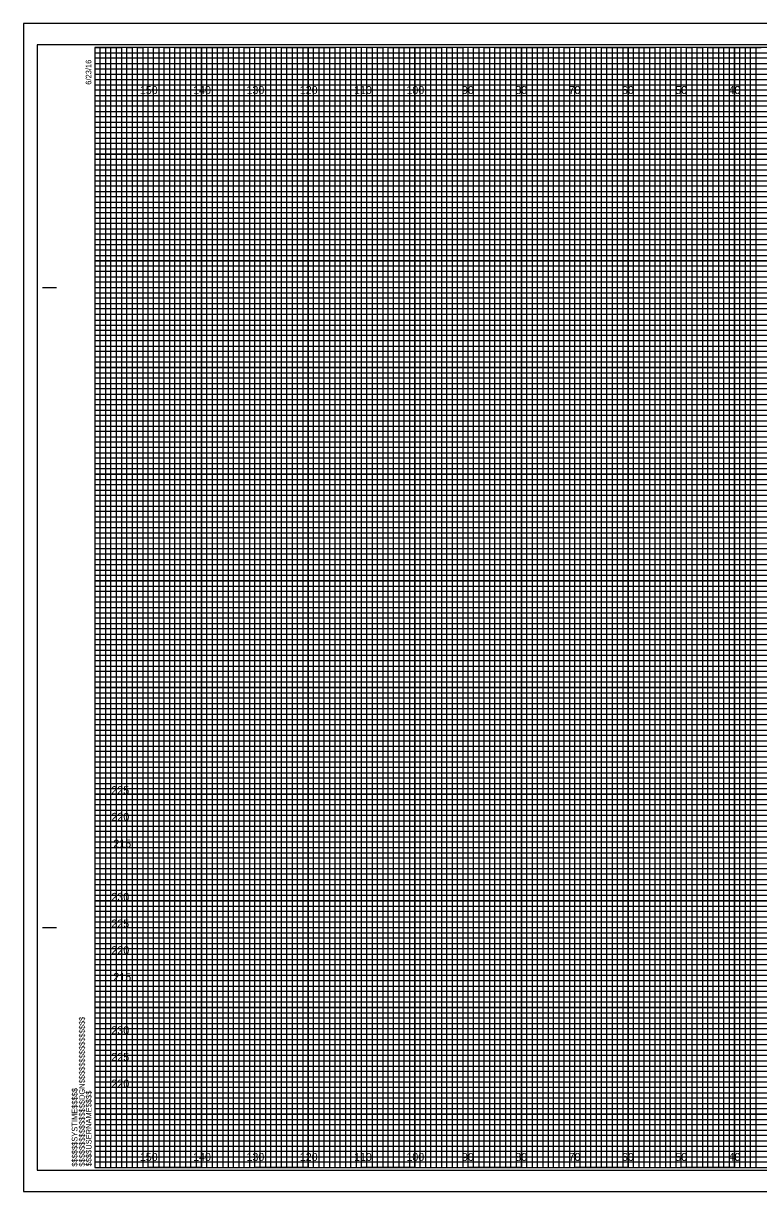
# Model space of a CAD drawing. Extents: x -13 to 323, y -5 to 434.
# Drawn here: x -13.4 to 124.5, y 215.5 to 434.5 of the extents above; entities that cross this region are included whole.
import ezdxf

# ---------------------------------------------------------------- set-up
doc = ezdxf.new("R2010")
doc.units = 0
for name, color, linetype in [('Prop XS Elevation Labels', 7, 'Continuous'), ('Prop XS Offset Labels', 7, 'Continuous'), ('Sheet Cross Section CELL', 7, 'Continuous'), ('Sheet Cross Section Grid Major CELL', 7, 'Continuous'), ('Sheet Cross Section Grid Middle CELL', 7, 'Continuous'), ('Sheet Cross Section Grid Minor 1 CELL', 7, 'Continuous'), ('Sheet Cross Section Grid Minor 2 CELL', 7, 'Continuous'), ('Sheet Cutting Line CELL', 7, 'Continuous'), ('Sheet DOT Grid CELL', 7, 'Continuous'), ('Sheet Plot Border Inside CELL', 7, 'Continuous'), ('Sheet Plot Border Outside CELL', 7, 'Continuous')]:
    doc.layers.add(name, color=color, linetype=linetype)

msp = doc.modelspace()

# ---------------------------------------------------------------- linework, layer by layer
at = {"layer": 'Sheet Cross Section CELL'}
for p, q in [((-9.8, 385), (-7.3, 385)), ((-9.7, 385), (-7.2, 385)), ((-9.8, 265), (-7.3, 265)), ((-9.7, 265), (-7.2, 265)), ((0, 220), (0, 220)), ((0, 220), (0, 220)), ((0, 220), (0, 220)), ((0, 220), (0, 220)), ((0, 220), (0, 220)), ((0, 220), (0, 220)), ((0, 220), (0, 220))]:
    msp.add_line(p, q, dxfattribs=at)
msp.add_lwpolyline([(320, 430), (0, 430), (0, 220), (320, 220)], close=True, dxfattribs=at)
at = {"layer": 'Sheet Cross Section Grid Major CELL'}
for p, q in [((10, 430), (0, 430)), ((10, 220), (10, 430)), ((30, 430), (20, 430)), ((20, 430), (20, 220)), ((30, 220), (30, 430)), ((50, 430), (40, 430)), ((40, 430), (40, 220)), ((50, 220), (50, 430)), ((70, 430), (60, 430)), ((60, 430), (60, 220)), ((70, 220), (70, 430)), ((90, 430), (80, 430)), ((80, 430), (80, 220)), ((90, 220), (90, 430)), ((110, 430), (100, 430)), ((100, 430), (100, 220)), ((110, 220), (110, 430)), ((130, 430), (120, 430)), ((120, 430), (120, 220)), ((20, 220), (10, 220)), ((40, 220), (30, 220)), ((60, 220), (50, 220)), ((80, 220), (70, 220)), ((100, 220), (90, 220)), ((120, 220), (110, 220))]:
    msp.add_line(p, q, dxfattribs=at)
for points in [[(0, 420), (320, 420), (320, 410), (0, 410)], [(0, 400), (320, 400), (320, 390), (0, 390)], [(0, 380), (320, 380), (320, 370), (0, 370)], [(0, 360), (320, 360), (320, 350), (0, 350)], [(0, 340), (320, 340), (320, 330), (0, 330)], [(0, 320), (320, 320), (320, 310), (0, 310)], [(0, 300), (320, 300), (320, 290), (0, 290)], [(0, 280), (320, 280), (320, 270), (0, 270)], [(0, 260), (320, 260), (320, 250), (0, 250)], [(0, 240), (320, 240), (320, 230), (0, 230)]]:
    msp.add_lwpolyline(points, dxfattribs=at)
at = {"layer": 'Sheet Cross Section Grid Middle CELL'}
for points in [[(0, 430), (5, 430), (5, 220), (15, 220), (15, 430), (25, 430), (25, 220), (35, 220), (35, 430), (45, 430), (45, 220), (55, 220), (55, 430), (65, 430), (65, 220), (75, 220), (75, 430), (85, 430), (85, 220), (95, 220), (95, 430), (105, 430), (105, 220), (115, 220), (115, 430), (125, 430)], [(0, 425), (275, 425)], [(0, 405), (320, 405), (320, 415), (0, 415)], [(0, 385), (320, 385), (320, 395), (0, 395)], [(0, 365), (320, 365), (320, 375), (0, 375)], [(0, 345), (320, 345), (320, 355), (0, 355)], [(0, 325), (320, 325), (320, 335), (0, 335)], [(0, 305), (320, 305), (320, 315), (0, 315)], [(0, 285), (320, 285), (320, 295), (0, 295)], [(0, 265), (320, 265), (320, 275), (0, 275)], [(0, 245), (320, 245), (320, 255), (0, 255)], [(0, 225), (320, 225), (320, 235), (0, 235)]]:
    msp.add_lwpolyline(points, dxfattribs=at)
at = {"layer": 'Sheet Cross Section Grid Minor 1 CELL'}
for p, q in [((0, 429), (260, 429)), ((260, 427.98), (0, 427.98)), ((0, 427.98), (0, 427)), ((0, 427), (260, 427)), ((260, 425.89), (0, 425.89)), ((0, 425.89), (0, 424)), ((0, 424), (320, 424))]:
    msp.add_line(p, q, dxfattribs=at)
for points in [[(0, 423), (270, 423), (320, 423), (320, 422), (0, 422)], [(0, 421), (320, 421), (320, 419), (0, 419)], [(0, 418), (320, 418), (320, 417), (0, 416.98)], [(0, 416), (320, 416), (320, 414), (0, 414)], [(0, 413), (320, 413), (320, 412), (0, 412)], [(0, 411), (320, 411), (320, 409), (0, 409)], [(0, 408), (320, 408), (320, 407), (0, 407)], [(0, 406), (320, 406), (320, 404), (0, 404)], [(0, 403), (320, 403), (320, 402), (0, 402)], [(0, 401), (320, 401), (320, 399), (0, 399)], [(0, 398), (320, 398), (320, 397), (0, 397)], [(0, 396), (320, 396), (320, 393.95), (320, 393), (320, 392), (0, 392)], [(0, 394), (320, 394), (320, 393), (0, 393)], [(0, 391), (320, 391), (320, 389), (0, 389.03)], [(0, 389.03), (320, 389), (320, 388), (0, 388)], [(0, 387), (320, 387), (320, 386), (0, 386)], [(0, 384), (320, 384), (320, 383), (0, 383)], [(0, 382), (320, 382), (320, 381), (0, 381)], [(-0.07, 378.89), (320, 378.89), (320, 377.88), (-0.07, 377.88)], [(0, 377), (320, 377), (320, 376), (0, 376)], [(0, 374), (320, 374), (320, 373), (0, 373)], [(0, 372), (320, 372), (320, 371), (0, 371)], [(0, 369), (320, 369), (320, 368), (0, 368)], [(0, 367), (320, 367), (320, 366), (0, 366)], [(0, 364), (320, 364), (320, 363), (0, 363)], [(0, 362), (320, 362), (320, 361), (0, 361)], [(0, 359), (320, 359), (319.99, 357.98), (0, 358)], [(0, 357), (320, 357), (320, 356), (0, 356)], [(0, 354), (320, 354), (320, 353), (0, 353)], [(0, 352), (320, 352), (320, 351), (0, 351)], [(0, 349), (320, 349), (320, 348), (0, 348)], [(0, 347), (320, 347), (320, 346), (0, 346)], [(0, 344), (320, 344), (320, 343), (0, 343)], [(0, 342), (320, 342), (320, 341), (0, 341)], [(0, 339), (320, 339), (320, 338), (0, 338)], [(0, 336.99), (320.07, 336.91), (320, 336), (0, 336)], [(0, 334), (320, 334), (320, 333), (0, 333)], [(0, 332), (320, 332), (320, 331), (0, 331)], [(0, 329), (320, 329), (320, 328), (0, 328)], [(0, 327), (320, 327), (320, 326), (0, 326)], [(0, 324), (320, 324), (320, 323), (0, 323)], [(0, 322), (320, 322), (320, 321), (0, 321)], [(0, 319), (320, 319), (320, 318), (0, 318)], [(0, 317), (320, 317), (320, 316), (0, 316)], [(0, 314), (320, 314), (320, 313), (0, 313)], [(0, 312), (320, 312), (320, 311), (0, 311)], [(0, 309), (320, 309), (320, 308), (0, 308)], [(0, 307), (320, 307), (320, 306), (0, 306)], [(0, 304), (320, 304), (320, 303), (0, 303)], [(0, 302), (320, 302), (320, 301), (0, 301)], [(0, 299), (320, 299), (319.99, 297.98), (0, 298)], [(0, 297), (320, 297), (320, 296), (0, 296)], [(0, 294), (320, 294), (320, 293), (0, 293)], [(0, 292), (320, 292), (320, 291), (0, 291)], [(0, 289), (320, 289), (320, 288), (0, 288)], [(0, 287), (320, 287), (320, 286), (0, 286)], [(0, 284), (320, 284), (320, 283), (0, 283)], [(0, 282), (320, 282), (320, 281), (0, 281)], [(0, 279), (320, 279), (320, 278), (0, 278)], [(0, 276.99), (320.07, 276.91), (320, 276), (0, 276)], [(0, 274), (320, 274), (320, 273), (0, 273)], [(0, 272), (320, 272), (320, 271), (0, 271)], [(0, 269), (320, 269), (320, 268), (0, 268)], [(0, 267), (320, 267), (320, 266), (0, 266)], [(0, 264), (320, 264), (320, 263), (0, 263)], [(0, 262), (320, 262), (320, 261), (0, 261)], [(0, 259), (320, 259), (320, 258), (0, 258)], [(0, 257), (320, 257), (320, 256), (0, 256)], [(0, 254), (320, 254), (320, 253), (0, 253)], [(0, 252), (320, 252), (320, 251), (0, 251)], [(0, 249), (320, 249), (320, 248), (0, 248)], [(0, 247), (320, 247), (320, 246), (0, 246)], [(0, 244), (320, 244), (320, 243), (0, 243)], [(0, 242), (320, 242), (320, 241), (0, 241)], [(0, 239), (320, 239), (320, 238), (0, 238)], [(0, 237), (320, 237), (320, 236), (0, 236)], [(0, 234), (320, 234), (320, 233), (0, 233)], [(0, 232), (320, 232), (320, 231), (0, 231)], [(0, 229), (320, 229), (320, 228), (0, 228)], [(0, 227), (320, 227), (320, 226), (0, 226)], [(0, 224), (320, 224), (320, 223), (0, 223)], [(0, 222), (320, 222), (320, 221), (0, 221)]]:
    msp.add_lwpolyline(points, dxfattribs=at)
at = {"layer": 'Sheet Cross Section Grid Minor 2 CELL'}
for points in [[(0, 220), (1, 220), (1, 430), (2, 430), (2, 220)], [(2, 220), (3, 220), (3, 430), (4, 430), (4, 220)], [(5, 220), (6, 220), (6, 430), (7, 430), (7, 220)], [(7, 220), (8, 220), (8, 430), (9, 430), (9, 220)], [(10, 220), (11, 220), (11, 430), (12, 430), (12, 220)], [(12, 220), (13, 220), (13, 430), (14, 430), (14, 220)], [(15, 220), (16, 220), (16, 430), (17, 430), (17, 220)], [(17, 220), (18, 220), (18, 430), (19, 430), (19, 220)], [(20, 220), (21, 220), (21, 430), (22, 430), (22, 220)], [(22, 220), (23, 220), (23, 430), (24, 430), (24, 220)], [(25, 220), (26, 220), (26, 430), (27, 430), (27, 220)], [(27, 220), (28, 220), (28, 430), (29, 430), (29, 220)], [(30, 220), (31, 220), (31, 430), (32, 430), (32, 220)], [(32, 220), (33, 220), (33, 430), (34, 430), (34, 220)], [(35, 220), (36, 220), (36, 430), (37, 430), (37, 220)], [(37, 220), (38, 220), (38, 430), (39, 430), (39, 220)], [(40, 220), (41, 220), (41, 430), (42, 430), (42, 220)], [(42, 220), (43, 220), (43, 430), (44, 430), (44, 220)], [(45, 220), (46, 220), (46, 430), (47, 430), (47, 220)], [(47, 220), (48, 220), (48, 430), (49, 430), (49, 220)], [(50, 220), (51, 220), (51, 430), (52, 430), (52, 220)], [(52, 220), (53, 220), (53, 430), (54, 430), (54, 220)], [(55, 220), (56, 220), (56, 430), (57, 430), (57, 220)], [(57, 220), (58, 220), (58, 430), (59, 430), (59, 220)], [(60, 220), (61, 220), (61, 430), (62, 430), (62, 220)], [(62, 220), (63, 220), (63, 430), (64, 430), (64, 220)], [(65, 220), (66, 220), (66, 430), (67, 430), (67, 220)], [(67, 220), (68, 220), (68, 430), (69, 430), (69, 220)], [(70, 220), (71, 220), (71, 430), (72, 430), (72, 220)], [(72, 220), (73, 220), (73, 430), (74, 430), (74, 220)], [(75, 220), (76, 220), (76, 430), (77, 430), (77, 220)], [(77, 220), (78, 220), (78, 430), (79, 430), (79, 220)], [(80, 220), (81, 220), (81, 430), (82, 430), (82, 220)], [(82, 220), (83, 220), (83, 430), (84, 430), (84, 220)], [(85, 220), (86, 220), (86, 430), (87, 430), (87, 220)], [(87, 220), (88, 220), (88, 430), (89, 430), (89, 220)], [(90, 220), (91, 220), (91, 430), (92, 430), (92, 220)], [(92, 220), (93, 220), (93, 430), (94, 430), (94, 220)], [(95, 220), (96, 220), (96, 430), (97, 430), (97, 220)], [(97, 220), (98, 220), (98, 430), (99, 430), (99, 220)], [(100, 220), (101, 220), (101, 430), (102, 430), (102, 220)], [(102, 220), (103, 220), (103, 430), (104, 430), (104, 220)], [(105, 220), (106, 220), (106, 430), (107, 430), (107, 220)], [(107, 220), (108, 220), (108, 430), (109, 430), (109, 220)], [(110, 220), (111, 220), (111, 430), (112, 430), (112, 220)], [(112, 220), (113, 220), (113, 430), (114, 430), (114, 220)], [(115, 220), (116, 220), (116, 430), (117, 430), (117, 220)], [(117, 220), (118, 220), (118, 430), (119, 430), (119, 220)], [(120, 220), (121, 220), (121, 430), (122, 430), (122, 220)], [(122, 220), (123, 220), (123, 430), (124, 430), (124, 220)]]:
    msp.add_lwpolyline(points, dxfattribs=at)
at = {"layer": 'Sheet Cutting Line CELL'}
for p, q in [((323.3, 434.5), (-13.4, 434.5)), ((-13.4, 434.5), (-13.4, 215.5)), ((-13.4, 215.5), (323.3, 215.5))]:
    msp.add_line(p, q, dxfattribs=at)
at = {"layer": 'Sheet DOT Grid CELL'}
for p, q in [((10, 220), (10, 430)), ((20, 220), (20, 430)), ((30, 220), (30, 430)), ((40, 220), (40, 430)), ((50, 220), (50, 430)), ((60, 220), (60, 430)), ((70, 220), (70, 430)), ((80, 220), (80, 430)), ((90, 220), (90, 430)), ((100, 220), (100, 430)), ((110, 220), (110, 430)), ((120, 220), (120, 430)), ((0, 420), (320, 420)), ((0, 410), (320, 410)), ((0, 400), (320, 400)), ((0, 390), (320, 390)), ((0, 380), (320, 380)), ((0, 370), (320, 370)), ((0, 360), (320, 360)), ((0, 350), (320, 350)), ((0, 340), (320, 340)), ((0, 330), (320, 330)), ((0, 320), (320, 320)), ((0, 310), (320, 310)), ((0, 300), (320, 300)), ((0, 290), (320, 290)), ((0, 280), (320, 280)), ((0, 270), (320, 270)), ((0, 260), (320, 260)), ((0, 250), (320, 250)), ((0, 240), (320, 240)), ((0, 230), (320, 230))]:
    msp.add_line(p, q, dxfattribs=at)
at = {"layer": 'Sheet Plot Border Inside CELL'}
msp.add_lwpolyline([(-10.8, 219.5), (322.4, 219.5), (322.4, 430.5), (-10.8, 430.5)], close=True, dxfattribs=at)
at = {"layer": 'Sheet Plot Border Outside CELL'}
msp.add_lwpolyline([(-13.4, 215.5), (323.3, 215.5), (323.3, 434.5), (-13.4, 434.5)], close=True, dxfattribs=at)

# ---------------------------------------------------------------- texts
at = {"layer": 'Prop XS Elevation Labels'}
for s, p in [('225', (3.1, 290)), ('220', (3.12, 285)), ('215', (3.48, 280)), ('230', (3.11, 270)), ('225', (3.1, 265)), ('220', (3.12, 260)), ('215', (3.48, 255)), ('230', (3.11, 245)), ('225', (3.1, 240)), ('220', (3.12, 235))]:
    msp.add_text(s, height=1.5, dxfattribs=at).set_placement(p)
at = {"layer": 'Prop XS Offset Labels'}
for s, p in [('150', (8.44, 421.25)), ('140', (18.44, 421.25)), ('130', (28.44, 421.25)), ('120', (38.44, 421.25)), ('110', (48.62, 421.25)), ('100', (58.44, 421.25)), ('90', (68.86, 421.25)), ('80', (78.86, 421.25)), ('70', (88.86, 421.25)), ('60', (98.86, 421.25)), ('50', (108.86, 421.25)), ('40', (118.86, 421.25)), ('150', (8.44, 221.25)), ('140', (18.44, 221.25)), ('130', (28.44, 221.25)), ('120', (38.44, 221.25)), ('110', (48.62, 221.25)), ('100', (58.44, 221.25)), ('90', (68.86, 221.25)), ('80', (78.86, 221.25)), ('70', (88.86, 221.25)), ('60', (98.86, 221.25)), ('50', (108.86, 221.25)), ('40', (118.86, 221.25))]:
    msp.add_text(s, height=1.5, dxfattribs=at).set_placement(p)
at = {"layer": 'Sheet Cross Section CELL'}
for s, p in [('6/23/16', (-0.65, 423)), ('$$$$$$$$$$$$$$$$DGN$$$$$$$$$$$$$$$$', (-1.88, 220.18)), ('$$$$$$SYSTIME$$$$$', (-3.26, 220.18)), ('$$$$USERNAME$$$$', (-0.62, 220.23))]:
    msp.add_text(s, height=1.05, rotation=90, dxfattribs=at).set_placement(p)

doc.saveas('drawing.dxf')
